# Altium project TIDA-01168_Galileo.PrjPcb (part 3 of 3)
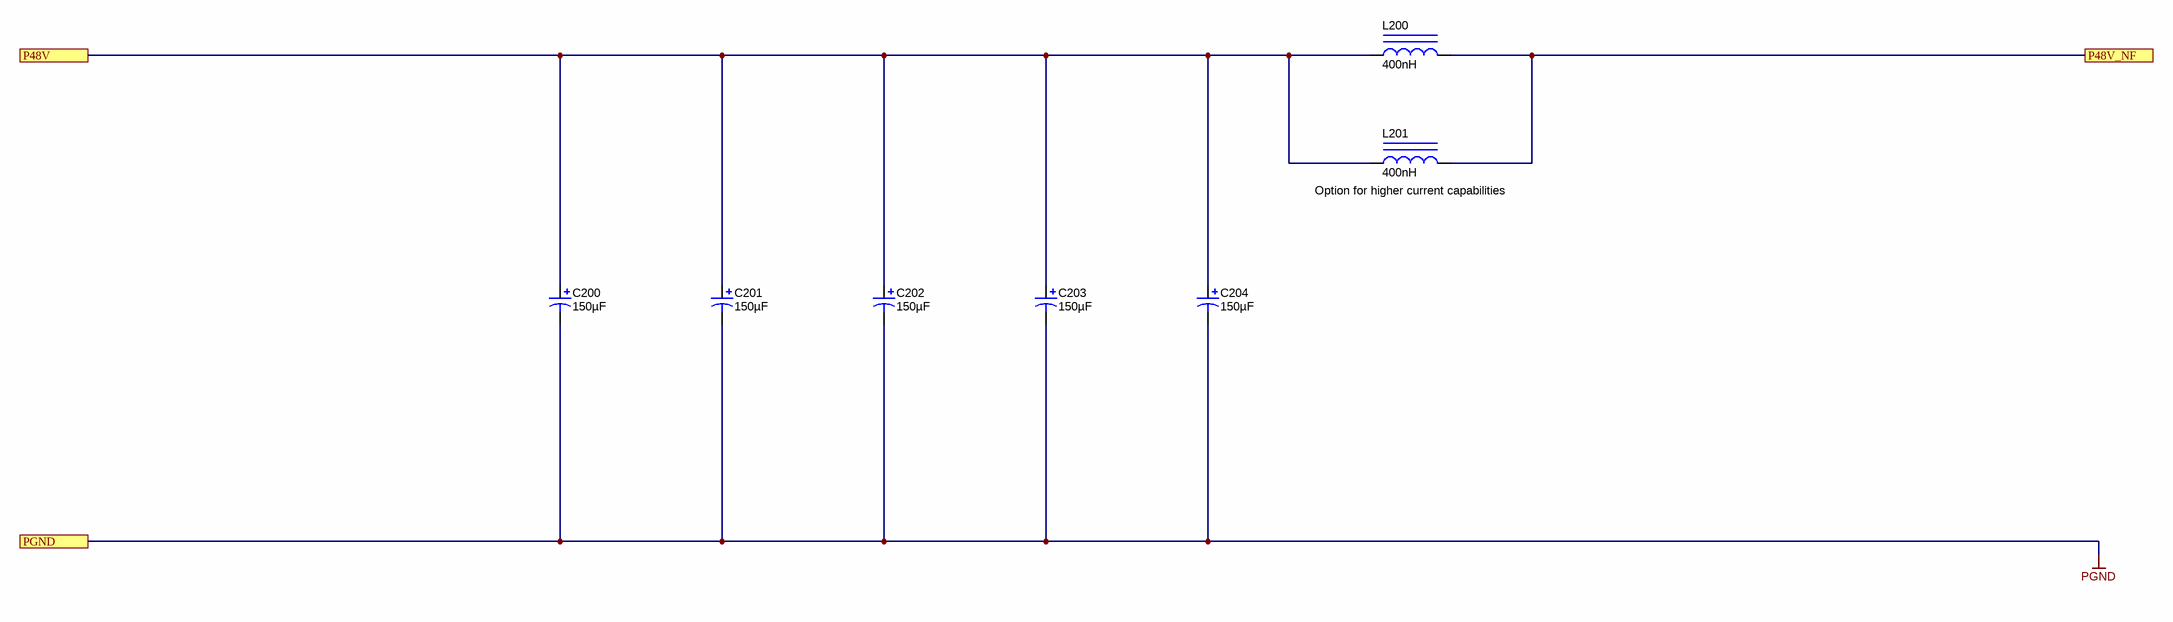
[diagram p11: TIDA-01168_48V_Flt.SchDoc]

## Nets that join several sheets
CS1B_A: PS (10 pins), TIDA-01168_12V_Brk (Q402.4 Q404.4 Q406.4 R405.1), LM (R904_LM2.2 R914_LM2.2), PS (10 pins), PS (10 pins), PS (10 pins), LM (R904_LM1.2 R914_LM1.2), TIDA-01168_If (J700.5 J700.7)
GND: TIDA-01168_Hierarchy (J3.1 J4.1), PS (24 pins), TIDA-01168_48V_Brk (15 pins), TIDA-01168_12V_Brk (7 pins), TIDA-01168_Diag (14 pins), TIDA-01168_Control (31 pins), LM (29 pins), TIDA-01168_BiasSupply (33 pins), PS (24 pins), PS (24 pins), PS (24 pins), LM (29 pins), TIDA-01168_If (21 pins), TIDA-01168_48V_Flt (5 pins)
KL30_BIAS: TIDA-01168_12V_Brk (D400.1), TIDA-01168_BiasSupply (C500.1 R500.2 U500.6)
P3V3: TIDA-01168_Diag (17 pins), TIDA-01168_Control (21 pins), TIDA-01168_BiasSupply (C519.1 R510.2 U503.1), TIDA-01168_If (6 pins)
P10V: TIDA-01168_Diag (R602.2), LM (6 pins), TIDA-01168_BiasSupply (C515.1 C516.2 R506.2 U502.6), LM (6 pins), TIDA-01168_If (J700.9 J700.11)
P48V: TIDA-01168_48V_Brk (6 pins), TIDA-01168_BiasSupply (D500.2), TIDA-01168_If (J700.1 J700.3), TIDA-01168_48V_Flt (7 pins)
VIN_LM: LM (C907_LM2.1 U900_LM2.6), TIDA-01168_BiasSupply (5 pins), LM (C907_LM1.1 U900_LM1.6)
ADCINA6: TIDA-01168_Control (R821.2), TIDA-01168_If (J702.13)
ADCINA7: TIDA-01168_Control (R823.2), TIDA-01168_If (J702.11)
ADCINB1: TIDA-01168_Control (R824.2), TIDA-01168_If (J702.7)
ADCINB2: TIDA-01168_Control (R825.2), TIDA-01168_If (J702.8 R700.1)
ADCINB3: TIDA-01168_Control (R826.2), TIDA-01168_If (J702.10)
ADCINB4: TIDA-01168_Control (R827.2), TIDA-01168_If (J702.12 R701.1)
ADCINB6: TIDA-01168_Control (R828.2), TIDA-01168_If (J702.14)
BRKG: TIDA-01168_12V_Brk (8 pins), LM (U900_LM2.34), LM (U900_LM1.34)
BRKS: TIDA-01168_12V_Brk (32 pins), LM (U900_LM2.33), LM (U900_LM1.33)
CLK: TIDA-01168_Control (R814.1), TIDA-01168_If (J701.5)
CS1A_A: LM (R901_LM2.2), PS (L300_PS3.1 R300_PS3.1)
CS1A_B: PS (L300_PS1.1 R300_PS1.1), LM (R901_LM1.2)
CS2A_A: PS (L300_PS4.1 R300_PS4.1), LM (R915_LM2.2)
CS2A_B: PS (L300_PS2.1 R300_PS2.1), LM (R915_LM1.2)
DIR: TIDA-01168_Control (R809.1 U800.1 U801.40), LM (U900_LM2.44), LM (U900_LM1.44)
EN1: TIDA-01168_Control (U801.28), LM (R916_LM2.1 U900_LM2.39)
EN1: TIDA-01168_Control (U801.38), LM (R916_LM1.1 U900_LM1.39)
EN2: TIDA-01168_Control (U801.37), LM (R917_LM2.1 U900_LM2.43)
EN2: TIDA-01168_Control (U801.39), LM (R917_LM1.1 U900_LM1.43)
EN12: TIDA-01168_12V_Brk (R402.1), TIDA-01168_If (J702.5)
EN48: TIDA-01168_48V_Brk (U100.5), TIDA-01168_If (J702.6)
HO1_A: LM (U900_LM2.22), PS (R302_PS3.1 R305_PS3.1)
HO1_B: PS (R302_PS1.1 R305_PS1.1), LM (U900_LM1.22)
HO2_A: PS (R302_PS4.1 R305_PS4.1), LM (U900_LM2.15)
HO2_B: PS (R302_PS2.1 R305_PS2.1), LM (U900_LM1.15)
IMON: TIDA-01168_Control (C800.1 R804.2 U801.18), LM (U900_LM2.37 U900_LM2.38), LM (U900_LM1.37 U900_LM1.38)
ISETD: TIDA-01168_Control (U801.29), LM (R911_LM2.2 U900_LM2.42), LM (R911_LM1.2 U900_LM1.42)
KL30: TIDA-01168_Hierarchy (J2.1), TIDA-01168_12V_Brk (10 pins)
KL30_M: TIDA-01168_12V_Brk (R405.2), TIDA-01168_Control (R831.2)
KL30_POL: TIDA-01168_12V_Brk (D400.2 Q400.3), TIDA-01168_Diag (R607.2)
KL31_M: TIDA-01168_12V_Brk (R406.2), TIDA-01168_Control (R829.2)
KL40: TIDA-01168_Hierarchy (J1.1), TIDA-01168_48V_Brk (10 pins)
KL40_M: TIDA-01168_48V_Brk (R109.2), TIDA-01168_Control (R819.2)
KL41_M: TIDA-01168_48V_Brk (R110.2), TIDA-01168_Control (R812.2)
LO1_A: LM (U900_LM2.20), PS (R306_PS3.2 R307_PS3.2)
LO1_B: PS (R306_PS1.2 R307_PS1.2), LM (U900_LM1.20)
LO2_A: PS (R306_PS4.2 R307_PS4.2), LM (U900_LM2.17)
LO2_B: PS (R306_PS2.2 R307_PS2.2), LM (U900_LM1.17)
nFAULT: TIDA-01168_Control (U800.3), LM (U900_LM2.27), LM (U900_LM1.27)
nRST: TIDA-01168_Diag (D602.1 R601.1 U601.5), TIDA-01168_Control (U801.3 U804.1)
OPT: TIDA-01168_Control (R808.1 U801.41), LM (U900_LM2.29), LM (U900_LM1.29)
P48V_NF: PS (12 pins), PS (12 pins), PS (12 pins), PS (12 pins), TIDA-01168_48V_Flt (L200.2 L201.2)
RXD: TIDA-01168_Control (R816.1), TIDA-01168_If (J701.6)
SCL: TIDA-01168_Diag (5 pins), TIDA-01168_Control (R817.1 U801.36), TIDA-01168_If (J701.14)
SDA: TIDA-01168_Diag (5 pins), TIDA-01168_Control (R818.1 U801.31), TIDA-01168_If (J701.12)
SIMO: TIDA-01168_Control (R810.1), TIDA-01168_If (J701.13)
SOMI: TIDA-01168_Control (R811.1), TIDA-01168_If (J701.11)
STEA: TIDA-01168_Control (R815.1), TIDA-01168_If (J701.7)
SW1_A: LM (C908_LM2.1 U900_LM2.24), PS (8 pins)
SW1_B: PS (8 pins), LM (C908_LM1.1 U900_LM1.24)
SW2_A: PS (8 pins), LM (C911_LM2.1 U900_LM2.13)
SW2_B: PS (8 pins), LM (C911_LM1.1 U900_LM1.13)
SYNCIN_B: TIDA-01168_Hierarchy (NT1.2), LM (U900_LM1.40)
SYNCOUT_A: TIDA-01168_Hierarchy (NT1.1), LM (R908_LM2.2 U900_LM2.41)
TXD: TIDA-01168_Control (R820.1), TIDA-01168_If (J701.8)
UVLO: TIDA-01168_Diag (D600.2 D601.2 D602.2 R600.1), TIDA-01168_Control (U801.19 U804.3), LM (U900_LM2.10), LM (U900_LM1.10)
WDT_TRIG: TIDA-01168_Diag (R603.1), TIDA-01168_Control (U801.47)

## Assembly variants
001: not fitted C106 C310_PS1 C310_PS2 C310_PS3 C310_PS4 C404 C519 C520 C902_LM1 C902_LM2 C904_LM1 C904_LM2 C914_LM1 C914_LM2 C916_LM1 C916_LM2 D104 FID1 FID2 FID3 L201 R108 R303_PS1 R303_PS2 R303_PS3 R303_PS4 R906_LM1 R906_LM2 RV400 U503; alternate parts L300_PS1 -> IHTH1125KZEB4R7M5A, L300_PS4 -> IHTH1125KZEB4R7M5A, L300_PS3 -> IHTH1125KZEB4R7M5A, L300_PS2 -> IHTH1125KZEB4R7M5A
